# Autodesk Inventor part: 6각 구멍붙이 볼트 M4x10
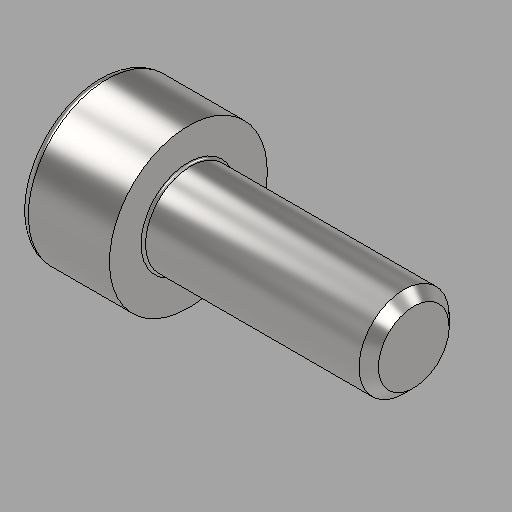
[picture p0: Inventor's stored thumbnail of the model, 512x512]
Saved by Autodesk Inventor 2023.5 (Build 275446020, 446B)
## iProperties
Created: 2025-07
Part Number: 6각 구멍붙이 볼트 M4x10
Material: 강철, 연강
Description: 6각머리 태핑 나사
Document SubType Name: Modeling
Designer: 1강의실14
Density: 7.85 g/cm^3
Appearance: 기본값
Author: jhkim
Sending System: Autodesk Inventor 2026
Preprocessor: ST-DEVELOPER v20.1
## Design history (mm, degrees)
feature "Solid1"
node "솔리드1"
